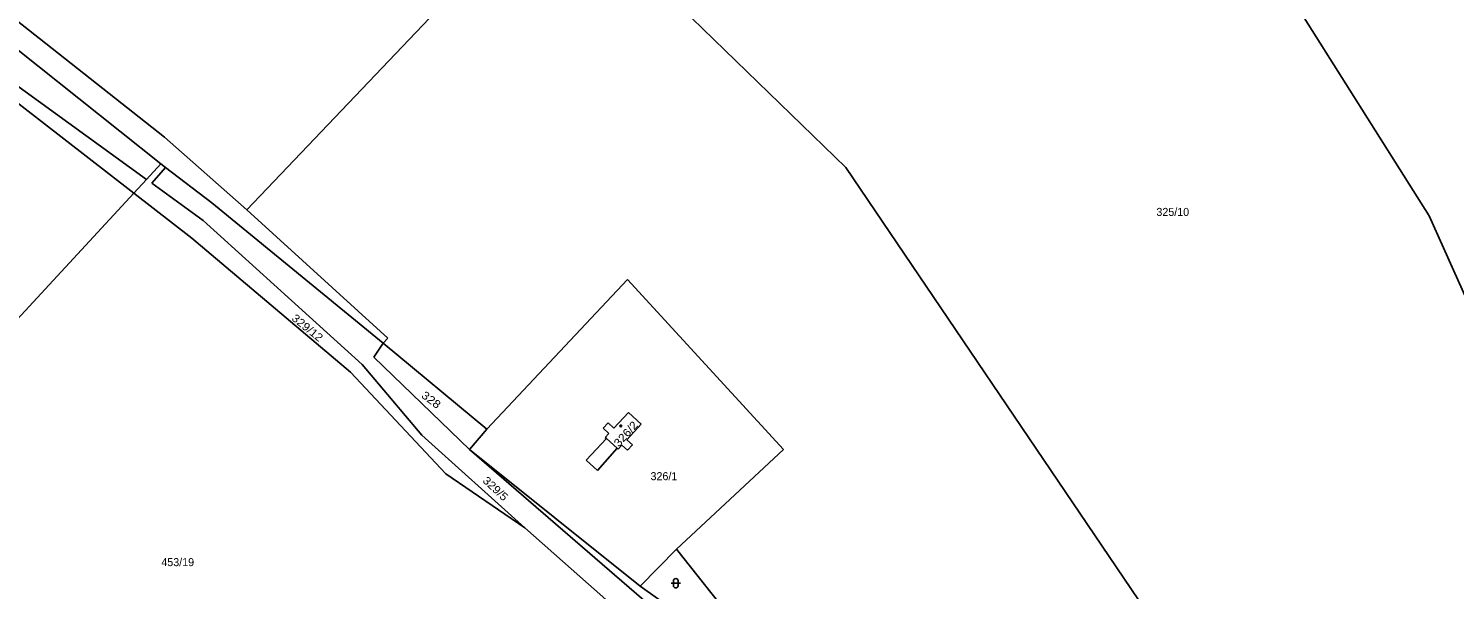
# Model space of a CAD drawing. Extents: x -633485 to -630509, y -1112692 to -1108818.
# Drawn here: x -632393.4 to -632090.4, y -1111466 to -1111346.9 of the extents above; entities that cross this region are included whole.
import ezdxf

# ---------------------------------------------------------------- set-up
doc = ezdxf.new("R2010")
doc.units = 0
doc.header["$LTSCALE"] = 0.68
for name, color, linetype, lineweight in [('1', 7, 'Continuous', 25), ('3', 7, 'Continuous', 25), ('4', 7, 'Continuous', 13), ('5', 7, 'Continuous', 25)]:
    doc.layers.add(name, color=color, linetype=linetype, lineweight=lineweight)
doc.layers.add('2', color=7, linetype='Continuous')

msp = doc.modelspace()

# ---------------------------------------------------------------- linework, layer by layer
at = {"layer": '1'}
for p, q in [((-632346.97, -1111385.42), (-632281.42, -1111316.6)), ((-632281.42, -1111316.6), (-632219.76, -1111376.4)), ((-632433.13, -1111321.62), (-632365.28, -1111375.66)), ((-632423.43, -1111323.49), (-632364.51, -1111369.98)), ((-632440.13, -1111328.27), (-632371, -1111381.84)), ((-632123.2, -1111343.29), (-632095.76, -1111386.68)), ((-632397.68, -1111357.67), (-632368.31, -1111378.93)), ((-632364.51, -1111369.98), (-632346.97, -1111385.42)), ((-632368.31, -1111378.93), (-632365.28, -1111375.66)), ((-632367.2, -1111379.73), (-632364.27, -1111376.43)), ((-632365.28, -1111375.66), (-632364.27, -1111376.43)), ((-632364.27, -1111376.43), (-632354.42, -1111383.92)), ((-632219.76, -1111376.4), (-632152.88, -1111475.08)), ((-632371, -1111381.84), (-632368.31, -1111378.93)), ((-632367.2, -1111379.73), (-632356.27, -1111387.64)), ((-632448.34, -1111465.44), (-632371, -1111381.84)), ((-632371, -1111381.84), (-632358.68, -1111391.39)), ((-632354.42, -1111383.92), (-632318.03, -1111413.69)), ((-632346.97, -1111385.42), (-632317.04, -1111412.65)), ((-632356.27, -1111387.64), (-632322.5, -1111418.21)), ((-632095.76, -1111386.68), (-632082.54, -1111416.33)), ((-632358.68, -1111391.39), (-632324.97, -1111419.84)), ((-632295.98, -1111431.99), (-632266.09, -1111400.2)), ((-632266.09, -1111400.2), (-632232.97, -1111436.29)), ((-632318.03, -1111413.69), (-632317.04, -1111412.65)), ((-632320.03, -1111416.68), (-632318.03, -1111413.69)), ((-632318.03, -1111413.69), (-632295.98, -1111431.99)), ((-632322.5, -1111418.21), (-632309.81, -1111433.28)), ((-632320.03, -1111416.68), (-632299.71, -1111436.26)), ((-632324.97, -1111419.84), (-632304.68, -1111441.48)), ((-632269, -1111431.75), (-632265.92, -1111428.4)), ((-632265.92, -1111428.4), (-632263.23, -1111430.88)), ((-632271.25, -1111431.74), (-632270.19, -1111430.61)), ((-632270.19, -1111430.61), (-632269, -1111431.75)), ((-632266.29, -1111434.22), (-632263.23, -1111430.88)), ((-632309.81, -1111433.28), (-632287.92, -1111452.93)), ((-632299.71, -1111436.26), (-632295.98, -1111431.99)), ((-632274.89, -1111438.56), (-632270.61, -1111433.94)), ((-632271.25, -1111431.74), (-632270.06, -1111432.88)), ((-632270.83, -1111433.74), (-632270.06, -1111432.88)), ((-632270.83, -1111433.74), (-632270.61, -1111433.94)), ((-632266.29, -1111434.22), (-632265.07, -1111435.3)), ((-632299.71, -1111436.26), (-632241.83, -1111486.19)), ((-632299.71, -1111436.26), (-632263.43, -1111465.33)), ((-632272.48, -1111440.74), (-632268.33, -1111436.01)), ((-632268.33, -1111436.01), (-632268.11, -1111436.21)), ((-632268.11, -1111436.21), (-632267.34, -1111435.36)), ((-632267.34, -1111435.36), (-632266.11, -1111436.43)), ((-632266.11, -1111436.43), (-632265.07, -1111435.3)), ((-632255.69, -1111457.44), (-632232.97, -1111436.29)), ((-632274.89, -1111438.56), (-632272.48, -1111440.74)), ((-632304.68, -1111441.48), (-632287.92, -1111452.93)), ((-632287.92, -1111452.93), (-632266.4, -1111471.99)), ((-632263.43, -1111465.33), (-632255.69, -1111457.44)), ((-632255.69, -1111457.44), (-632234.96, -1111483.58)), ((-632263.43, -1111465.33), (-632249.61, -1111475.04))]:
    msp.add_line(p, q, dxfattribs=at)
at = {"layer": '3'}
for p, q in [((-632256.861, -1111464.691), (-632254.859, -1111464.691)), ((-632256.361, -1111464.191), (-632256.361, -1111465.192)), ((-632255.359, -1111465.192), (-632255.359, -1111464.191))]:
    msp.add_line(p, q, dxfattribs=at)
for centre, start, end in [((-632255.86, -1111464.1909), 0, 180), ((-632255.86, -1111465.1909), 180, 359.98789)]:
    msp.add_arc(centre, 0.5, start, end, dxfattribs=at)
at = {"layer": '4'}
msp.add_line((-632270.61, -1111433.94), (-632268.33, -1111436.01), dxfattribs=at)
at = {"layer": '5'}
msp.add_circle((-632267.5468, -1111431.2692), 0.175, dxfattribs=at)

# ---------------------------------------------------------------- texts
at = {"layer": '2'}
for s, p in [('325/10', (-632153.74, -1111386.695)), ('326/1', (-632261.22, -1111442.805)), ('453/19', (-632365.15, -1111461.055))]:
    msp.add_text(s, height=1.7, dxfattribs=at).set_placement(p)
for s, rotation, width, p in [('329/12', 321, 1.1, (-632337.617, -1111408.7)), ('328', 323, 1.15, (-632310.075, -1111425.109)), ('326/2', 48, 1.1, (-632267.934, -1111435.874)), ('329/5', 317, 1.1, (-632297.039, -1111443.09))]:
    msp.add_text(s, height=1.7, rotation=rotation, dxfattribs=dict(at, width=width)).set_placement(p)

doc.saveas('drawing.dxf')
